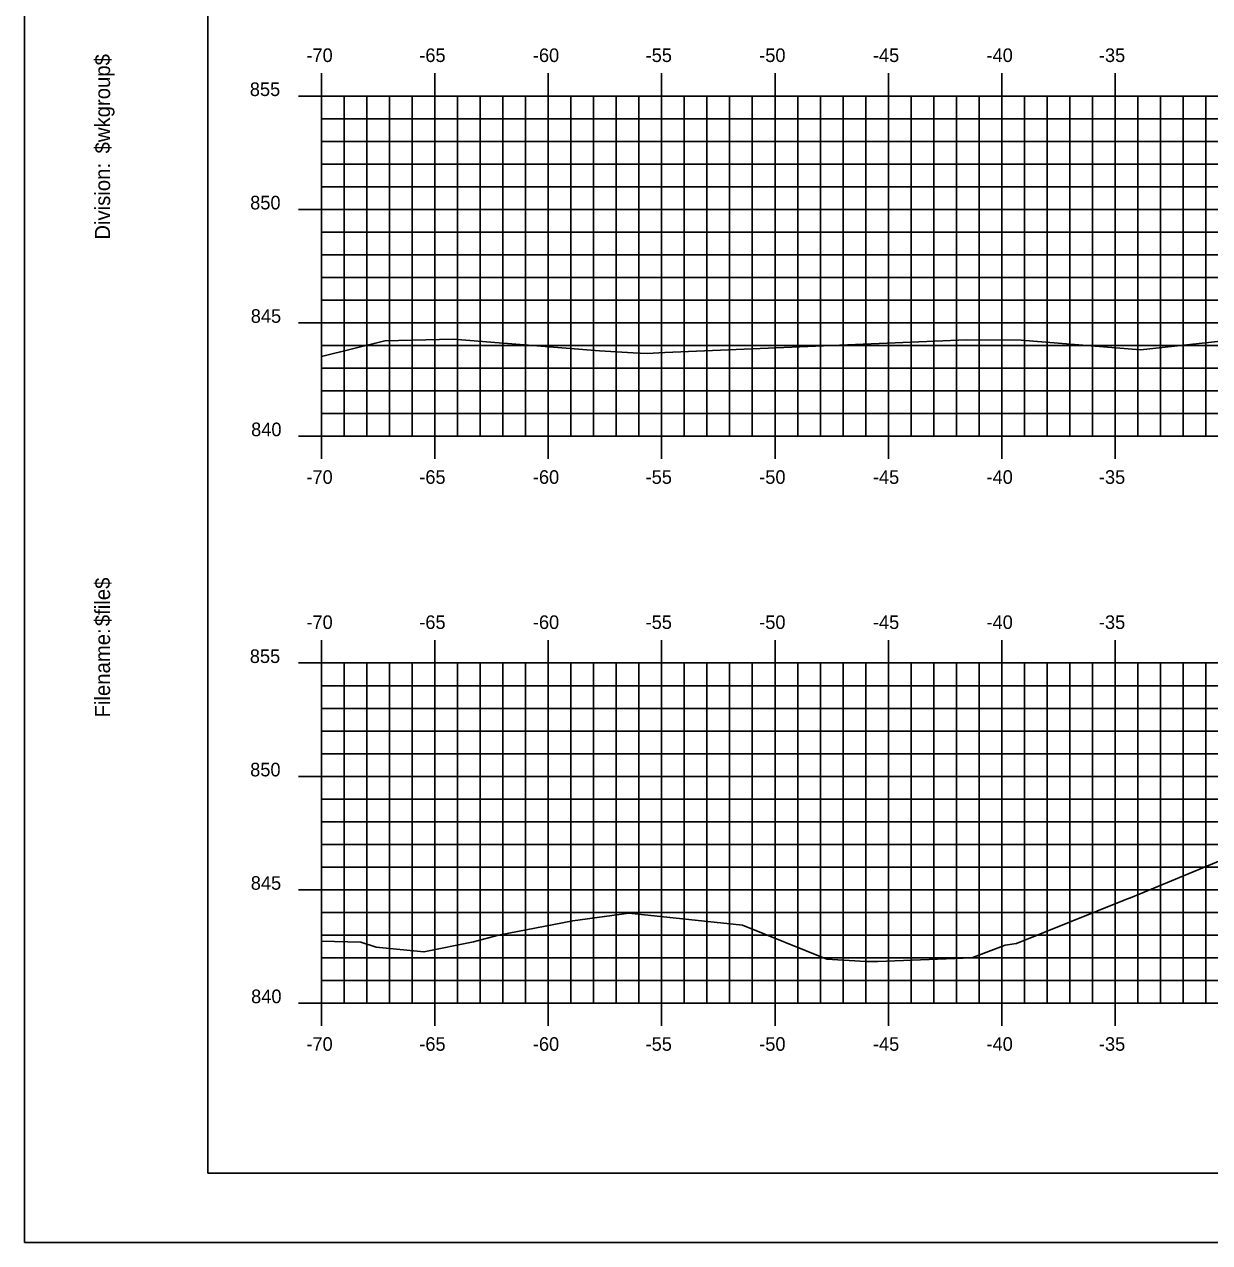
# Model space of a CAD drawing. Extents: x 2194256 to 2194747, y 863888 to 863998.
# Drawn here: x 2194393.6 to 2194445.9, y 863888.4 to 863942.1 of the extents above; entities that cross this region are included whole.
import ezdxf

# ---------------------------------------------------------------- set-up
doc = ezdxf.new("R2010")
doc.units = 0
for name, color, linetype in [('BORDER', 7, 'Continuous'), ('H_V ANNOTATION', 7, 'Continuous'), ('MAJOR', 7, 'Continuous'), ('MINOR', 7, 'Continuous'), ('PLOT BOUNDARY', 7, 'Continuous'), ('S_Roadway_Centerline', 7, 'Continuous')]:
    doc.layers.add(name, color=color, linetype=linetype)

msp = doc.modelspace()

# ---------------------------------------------------------------- linework, layer by layer
at = {"layer": 'BORDER'}
msp.add_lwpolyline([(2194401.743, 863891.446), (2194561.743, 863891.446), (2194561.743, 863996.446), (2194401.743, 863996.446)], close=True, dxfattribs=at)
at = {"layer": 'MAJOR'}
for p, q in [((2194406.743, 863939.948), (2194406.743, 863938.946)), ((2194411.743, 863939.948), (2194411.743, 863938.946)), ((2194416.743, 863939.948), (2194416.743, 863938.946)), ((2194421.743, 863939.948), (2194421.743, 863938.946)), ((2194426.743, 863939.948), (2194426.743, 863938.946)), ((2194431.743, 863939.948), (2194431.743, 863938.946)), ((2194436.743, 863939.948), (2194436.743, 863938.946)), ((2194441.743, 863939.948), (2194441.743, 863938.946)), ((2194405.741, 863938.946), (2194406.743, 863938.946)), ((2194406.743, 863938.946), (2194546.743, 863938.946)), ((2194406.743, 863923.946), (2194406.743, 863938.946)), ((2194406.743, 863923.946), (2194406.743, 863938.946)), ((2194411.743, 863923.946), (2194411.743, 863938.946)), ((2194416.743, 863923.946), (2194416.743, 863938.946)), ((2194421.743, 863923.946), (2194421.743, 863938.946)), ((2194426.743, 863923.946), (2194426.743, 863938.946)), ((2194431.743, 863923.946), (2194431.743, 863938.946)), ((2194436.743, 863923.946), (2194436.743, 863938.946)), ((2194441.743, 863923.946), (2194441.743, 863938.946)), ((2194405.741, 863933.946), (2194406.743, 863933.946)), ((2194406.743, 863933.946), (2194546.743, 863933.946)), ((2194405.741, 863928.946), (2194406.743, 863928.946)), ((2194406.743, 863928.946), (2194546.743, 863928.946)), ((2194405.741, 863923.946), (2194406.743, 863923.946)), ((2194406.743, 863923.946), (2194546.743, 863923.946)), ((2194406.743, 863922.944), (2194406.743, 863923.946)), ((2194411.743, 863922.944), (2194411.743, 863923.946)), ((2194416.743, 863922.944), (2194416.743, 863923.946)), ((2194421.743, 863922.944), (2194421.743, 863923.946)), ((2194426.743, 863922.944), (2194426.743, 863923.946)), ((2194431.743, 863922.944), (2194431.743, 863923.946)), ((2194436.743, 863922.944), (2194436.743, 863923.946)), ((2194441.743, 863922.944), (2194441.743, 863923.946)), ((2194406.743, 863914.948), (2194406.743, 863913.946)), ((2194411.743, 863914.948), (2194411.743, 863913.946)), ((2194416.743, 863914.948), (2194416.743, 863913.946)), ((2194421.743, 863914.948), (2194421.743, 863913.946)), ((2194426.743, 863914.948), (2194426.743, 863913.946)), ((2194431.743, 863914.948), (2194431.743, 863913.946)), ((2194436.743, 863914.948), (2194436.743, 863913.946)), ((2194441.743, 863914.948), (2194441.743, 863913.946)), ((2194405.741, 863913.946), (2194406.743, 863913.946)), ((2194406.743, 863913.946), (2194546.743, 863913.946)), ((2194406.743, 863898.946), (2194406.743, 863913.946)), ((2194406.743, 863898.946), (2194406.743, 863913.946)), ((2194411.743, 863898.946), (2194411.743, 863913.946)), ((2194416.743, 863898.946), (2194416.743, 863913.946)), ((2194421.743, 863898.946), (2194421.743, 863913.946)), ((2194426.743, 863898.946), (2194426.743, 863913.946)), ((2194431.743, 863898.946), (2194431.743, 863913.946)), ((2194436.743, 863898.946), (2194436.743, 863913.946)), ((2194441.743, 863898.946), (2194441.743, 863913.946)), ((2194405.741, 863908.946), (2194406.743, 863908.946)), ((2194406.743, 863908.946), (2194546.743, 863908.946)), ((2194405.741, 863903.946), (2194406.743, 863903.946)), ((2194406.743, 863903.946), (2194546.743, 863903.946)), ((2194405.741, 863898.946), (2194406.743, 863898.946)), ((2194406.743, 863898.946), (2194546.743, 863898.946)), ((2194406.743, 863897.944), (2194406.743, 863898.946)), ((2194411.743, 863897.944), (2194411.743, 863898.946)), ((2194416.743, 863897.944), (2194416.743, 863898.946)), ((2194421.743, 863897.944), (2194421.743, 863898.946)), ((2194426.743, 863897.944), (2194426.743, 863898.946)), ((2194431.743, 863897.944), (2194431.743, 863898.946)), ((2194436.743, 863897.944), (2194436.743, 863898.946)), ((2194441.743, 863897.944), (2194441.743, 863898.946))]:
    msp.add_line(p, q, dxfattribs=at)
at = {"layer": 'MINOR'}
for p, q in [((2194407.743, 863923.946), (2194407.743, 863938.946)), ((2194408.743, 863923.946), (2194408.743, 863938.946)), ((2194409.743, 863923.946), (2194409.743, 863938.946)), ((2194410.743, 863923.946), (2194410.743, 863938.946)), ((2194412.743, 863923.946), (2194412.743, 863938.946)), ((2194413.743, 863923.946), (2194413.743, 863938.946)), ((2194414.743, 863923.946), (2194414.743, 863938.946)), ((2194415.743, 863923.946), (2194415.743, 863938.946)), ((2194417.743, 863923.946), (2194417.743, 863938.946)), ((2194418.743, 863923.946), (2194418.743, 863938.946)), ((2194419.743, 863923.946), (2194419.743, 863938.946)), ((2194420.743, 863923.946), (2194420.743, 863938.946)), ((2194422.743, 863923.946), (2194422.743, 863938.946)), ((2194423.743, 863923.946), (2194423.743, 863938.946)), ((2194424.743, 863923.946), (2194424.743, 863938.946)), ((2194425.743, 863923.946), (2194425.743, 863938.946)), ((2194427.743, 863923.946), (2194427.743, 863938.946)), ((2194428.743, 863923.946), (2194428.743, 863938.946)), ((2194429.743, 863923.946), (2194429.743, 863938.946)), ((2194430.743, 863923.946), (2194430.743, 863938.946)), ((2194432.743, 863923.946), (2194432.743, 863938.946)), ((2194433.743, 863923.946), (2194433.743, 863938.946)), ((2194434.743, 863923.946), (2194434.743, 863938.946)), ((2194435.743, 863923.946), (2194435.743, 863938.946)), ((2194437.743, 863923.946), (2194437.743, 863938.946)), ((2194438.743, 863923.946), (2194438.743, 863938.946)), ((2194439.743, 863923.946), (2194439.743, 863938.946)), ((2194440.743, 863923.946), (2194440.743, 863938.946)), ((2194442.743, 863923.946), (2194442.743, 863938.946)), ((2194443.743, 863923.946), (2194443.743, 863938.946)), ((2194444.743, 863923.946), (2194444.743, 863938.946)), ((2194445.743, 863923.946), (2194445.743, 863938.946)), ((2194406.743, 863937.946), (2194546.743, 863937.946)), ((2194406.743, 863937.946), (2194407.745, 863937.946)), ((2194406.743, 863936.946), (2194546.743, 863936.946)), ((2194406.743, 863936.946), (2194407.745, 863936.946)), ((2194406.743, 863935.946), (2194546.743, 863935.946)), ((2194406.743, 863935.946), (2194407.745, 863935.946)), ((2194406.743, 863934.946), (2194546.743, 863934.946)), ((2194406.743, 863934.946), (2194407.745, 863934.946)), ((2194406.743, 863932.946), (2194546.743, 863932.946)), ((2194406.743, 863932.946), (2194407.745, 863932.946)), ((2194406.743, 863931.946), (2194546.743, 863931.946)), ((2194406.743, 863931.946), (2194407.745, 863931.946)), ((2194406.743, 863930.946), (2194546.743, 863930.946)), ((2194406.743, 863930.946), (2194407.745, 863930.946)), ((2194406.743, 863929.946), (2194546.743, 863929.946)), ((2194406.743, 863929.946), (2194407.745, 863929.946)), ((2194406.743, 863927.946), (2194546.743, 863927.946)), ((2194406.743, 863927.946), (2194407.745, 863927.946)), ((2194406.743, 863926.946), (2194546.743, 863926.946)), ((2194406.743, 863926.946), (2194407.745, 863926.946)), ((2194406.743, 863925.946), (2194546.743, 863925.946)), ((2194406.743, 863925.946), (2194407.745, 863925.946)), ((2194406.743, 863924.946), (2194546.743, 863924.946)), ((2194406.743, 863924.946), (2194407.745, 863924.946)), ((2194407.743, 863898.946), (2194407.743, 863913.946)), ((2194408.743, 863898.946), (2194408.743, 863913.946)), ((2194409.743, 863898.946), (2194409.743, 863913.946)), ((2194410.743, 863898.946), (2194410.743, 863913.946)), ((2194412.743, 863898.946), (2194412.743, 863913.946)), ((2194413.743, 863898.946), (2194413.743, 863913.946)), ((2194414.743, 863898.946), (2194414.743, 863913.946)), ((2194415.743, 863898.946), (2194415.743, 863913.946)), ((2194417.743, 863898.946), (2194417.743, 863913.946)), ((2194418.743, 863898.946), (2194418.743, 863913.946)), ((2194419.743, 863898.946), (2194419.743, 863913.946)), ((2194420.743, 863898.946), (2194420.743, 863913.946)), ((2194422.743, 863898.946), (2194422.743, 863913.946)), ((2194423.743, 863898.946), (2194423.743, 863913.946)), ((2194424.743, 863898.946), (2194424.743, 863913.946)), ((2194425.743, 863898.946), (2194425.743, 863913.946)), ((2194427.743, 863898.946), (2194427.743, 863913.946)), ((2194428.743, 863898.946), (2194428.743, 863913.946)), ((2194429.743, 863898.946), (2194429.743, 863913.946)), ((2194430.743, 863898.946), (2194430.743, 863913.946)), ((2194432.743, 863898.946), (2194432.743, 863913.946)), ((2194433.743, 863898.946), (2194433.743, 863913.946)), ((2194434.743, 863898.946), (2194434.743, 863913.946)), ((2194435.743, 863898.946), (2194435.743, 863913.946)), ((2194437.743, 863898.946), (2194437.743, 863913.946)), ((2194438.743, 863898.946), (2194438.743, 863913.946)), ((2194439.743, 863898.946), (2194439.743, 863913.946)), ((2194440.743, 863898.946), (2194440.743, 863913.946)), ((2194442.743, 863898.946), (2194442.743, 863913.946)), ((2194443.743, 863898.946), (2194443.743, 863913.946)), ((2194444.743, 863898.946), (2194444.743, 863913.946)), ((2194445.743, 863898.946), (2194445.743, 863913.946)), ((2194406.743, 863912.946), (2194546.743, 863912.946)), ((2194406.743, 863912.946), (2194407.745, 863912.946)), ((2194406.743, 863911.946), (2194546.743, 863911.946)), ((2194406.743, 863911.946), (2194407.745, 863911.946)), ((2194406.743, 863910.946), (2194546.743, 863910.946)), ((2194406.743, 863910.946), (2194407.745, 863910.946)), ((2194406.743, 863909.946), (2194546.743, 863909.946)), ((2194406.743, 863909.946), (2194407.745, 863909.946)), ((2194406.743, 863907.946), (2194546.743, 863907.946)), ((2194406.743, 863907.946), (2194407.745, 863907.946)), ((2194406.743, 863906.946), (2194546.743, 863906.946)), ((2194406.743, 863906.946), (2194407.745, 863906.946)), ((2194406.743, 863905.946), (2194546.743, 863905.946)), ((2194406.743, 863905.946), (2194407.745, 863905.946)), ((2194406.743, 863904.946), (2194546.743, 863904.946)), ((2194406.743, 863904.946), (2194407.745, 863904.946)), ((2194406.743, 863902.946), (2194546.743, 863902.946)), ((2194406.743, 863902.946), (2194407.745, 863902.946)), ((2194406.743, 863901.946), (2194546.743, 863901.946)), ((2194406.743, 863901.946), (2194407.745, 863901.946)), ((2194406.743, 863900.946), (2194546.743, 863900.946)), ((2194406.743, 863900.946), (2194407.745, 863900.946)), ((2194406.743, 863899.946), (2194546.743, 863899.946)), ((2194406.743, 863899.946), (2194407.745, 863899.946))]:
    msp.add_line(p, q, dxfattribs=at)
at = {"layer": 'PLOT BOUNDARY'}
msp.add_lwpolyline([(2194393.65, 863888.387), (2194563.65, 863888.387), (2194563.65, 863998.387), (2194393.65, 863998.387)], close=True, dxfattribs=at)
at = {"layer": 'S_Roadway_Centerline'}
for points in [[(2194406.743, 863927.457), (2194409.545, 863928.154), (2194412.555, 863928.227), (2194419.007, 863927.705), (2194420.488, 863927.623), (2194421.11, 863927.596), (2194421.886, 863927.644), (2194435.191, 863928.197), (2194437.603, 863928.188), (2194442.863, 863927.76), (2194449.251, 863928.439)], [(2194406.743, 863901.683), (2194408.485, 863901.631), (2194409.158, 863901.412), (2194411.266, 863901.206), (2194413.456, 863901.645), (2194414.547, 863901.94), (2194417.827, 863902.578), (2194420.306, 863902.916), (2194425.314, 863902.379), (2194429.025, 863900.891), (2194430.744, 863900.786), (2194431.275, 863900.779), (2194435.427, 863900.944), (2194436.894, 863901.503), (2194437.386, 863901.578), (2194442.143, 863903.486), (2194442.28, 863903.548), (2194442.413, 863903.585), (2194454.389, 863908.554)]]:
    msp.add_lwpolyline(points, dxfattribs=at)

# ---------------------------------------------------------------- texts
at = {"layer": 'BORDER'}
for s, p in [('$wkgroup$', (2194397.428, 863936.415)), ('Division:', (2194397.428, 863932.612)), ('$file$', (2194397.428, 863915.571)), ('Filename:', (2194397.428, 863911.544))]:
    msp.add_text(s, height=0.6696, rotation=90, dxfattribs=at).set_placement(p)
at = {"layer": 'H_V ANNOTATION'}
for s, p in [('-70', (2194406.084, 863940.446)), ('-65', (2194411.06, 863940.446)), ('-60', (2194416.068, 863940.446)), ('-55', (2194421.039, 863940.446)), ('-50', (2194426.047, 863940.446)), ('-45', (2194431.06, 863940.446)), ('-40', (2194436.068, 863940.446)), ('-35', (2194441.023, 863940.446)), ('855', (2194403.589, 863938.946)), ('850', (2194403.605, 863933.946)), ('845', (2194403.632, 863928.946)), ('840', (2194403.648, 863923.946)), ('-70', (2194406.084, 863921.846)), ('-65', (2194411.06, 863921.846)), ('-60', (2194416.068, 863921.846)), ('-55', (2194421.039, 863921.846)), ('-50', (2194426.047, 863921.846)), ('-45', (2194431.06, 863921.846)), ('-40', (2194436.068, 863921.846)), ('-35', (2194441.023, 863921.846)), ('-70', (2194406.084, 863915.446)), ('-65', (2194411.06, 863915.446)), ('-60', (2194416.068, 863915.446)), ('-55', (2194421.039, 863915.446)), ('-50', (2194426.047, 863915.446)), ('-45', (2194431.06, 863915.446)), ('-40', (2194436.068, 863915.446)), ('-35', (2194441.023, 863915.446)), ('855', (2194403.589, 863913.946)), ('850', (2194403.605, 863908.946)), ('845', (2194403.632, 863903.946)), ('840', (2194403.648, 863898.946)), ('-70', (2194406.084, 863896.846)), ('-65', (2194411.06, 863896.846)), ('-60', (2194416.068, 863896.846)), ('-55', (2194421.039, 863896.846)), ('-50', (2194426.047, 863896.846)), ('-45', (2194431.06, 863896.846)), ('-40', (2194436.068, 863896.846)), ('-35', (2194441.023, 863896.846))]:
    msp.add_text(s, height=0.6, dxfattribs=at).set_placement(p)

doc.saveas('drawing.dxf')
